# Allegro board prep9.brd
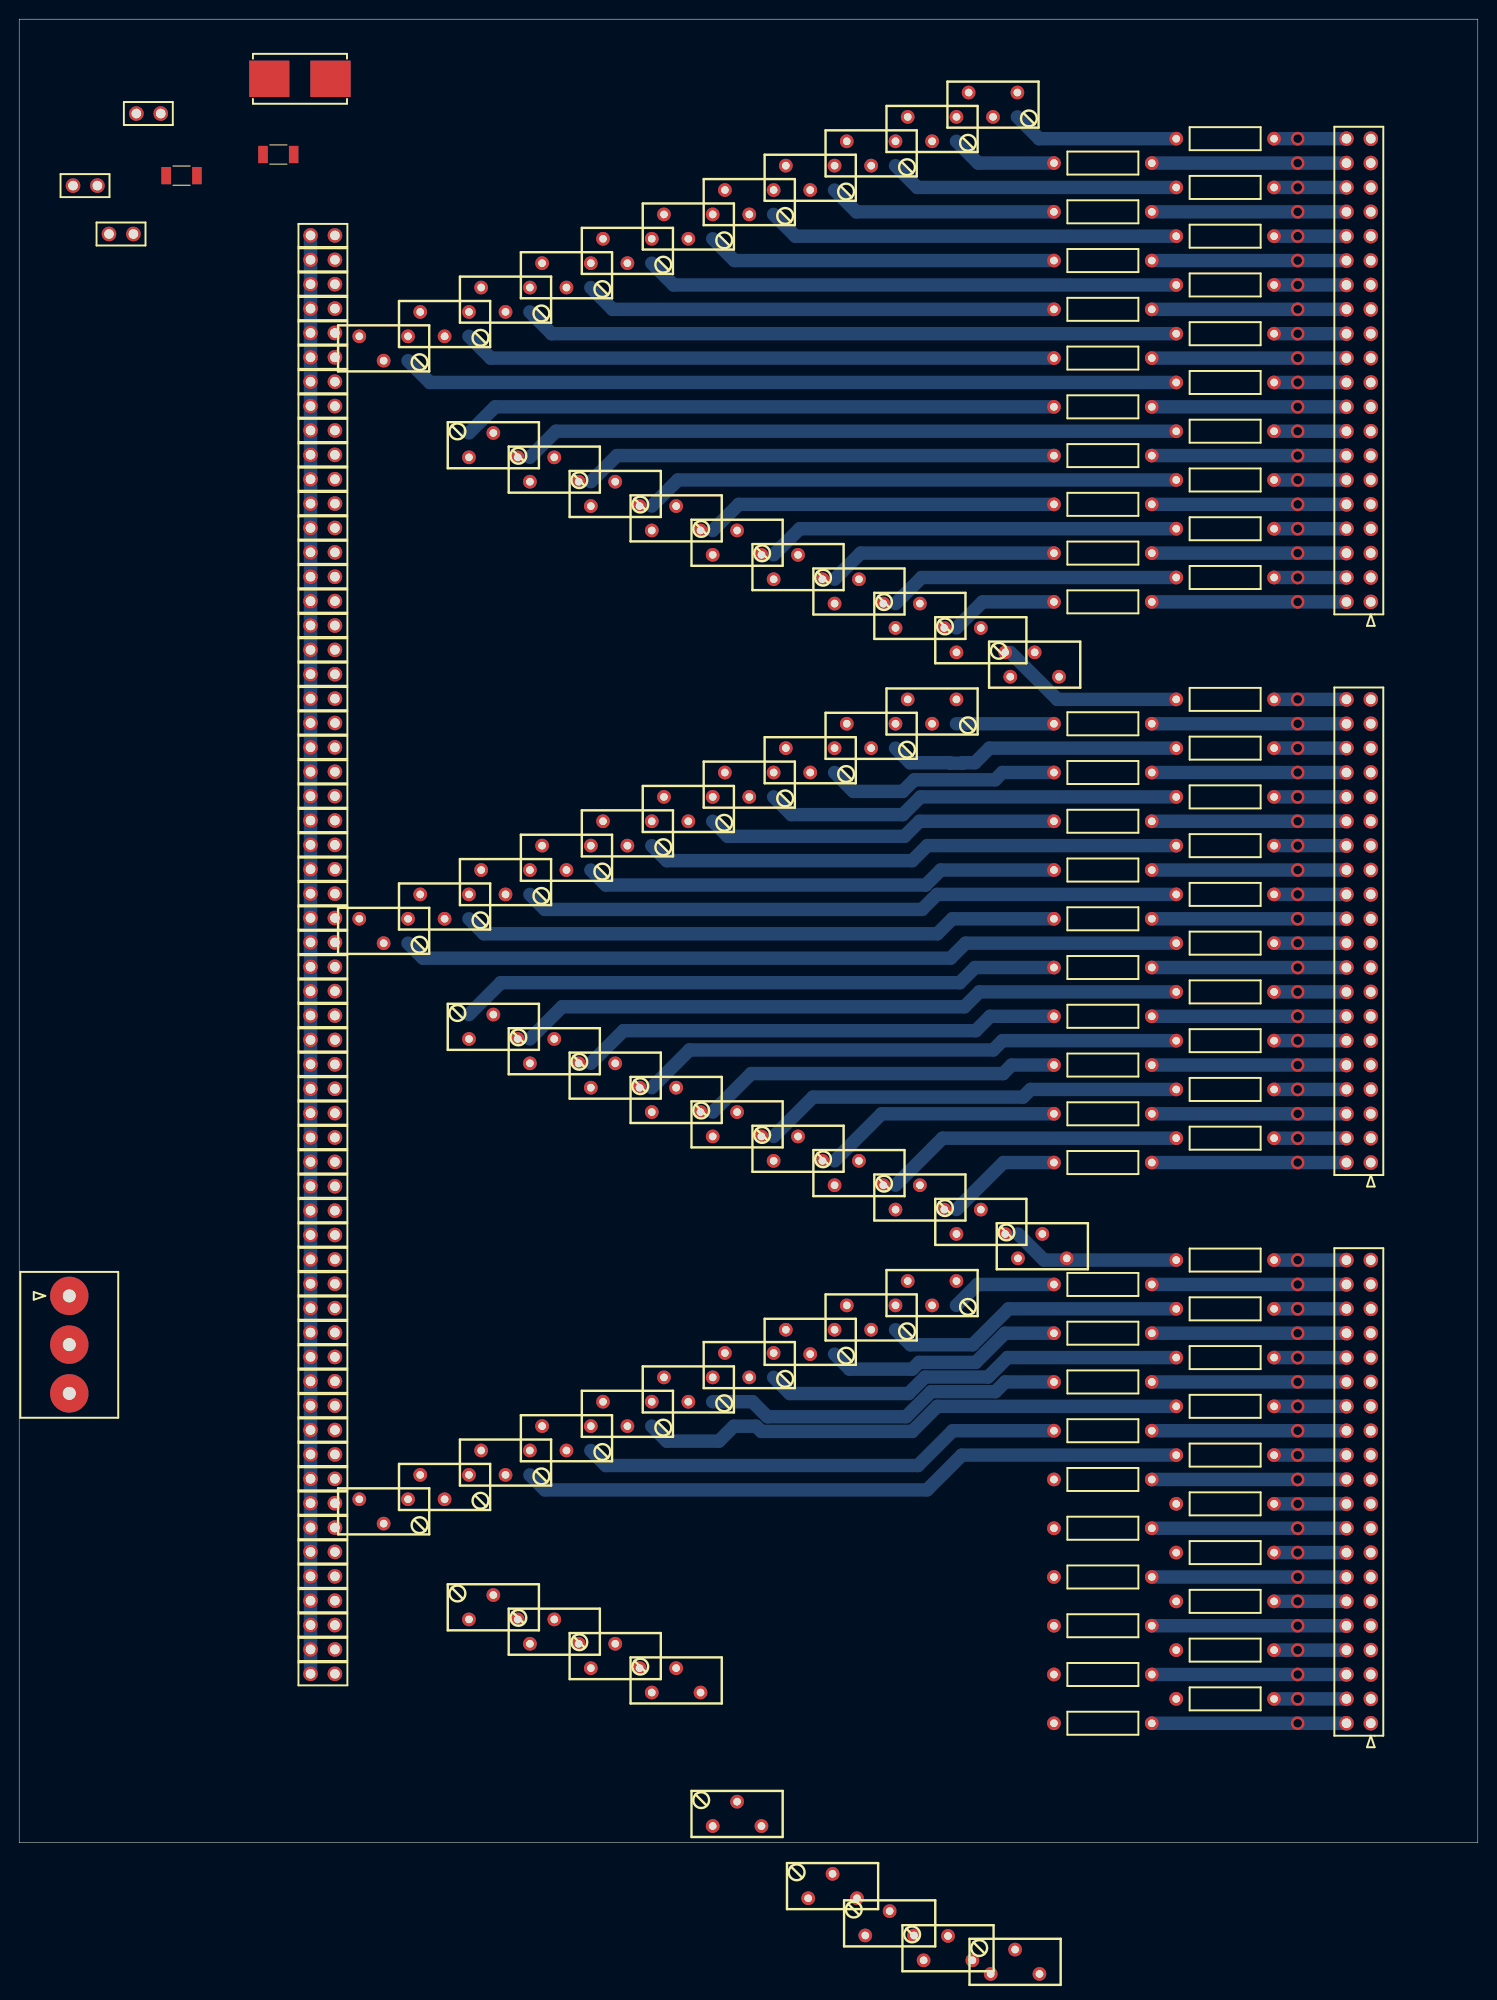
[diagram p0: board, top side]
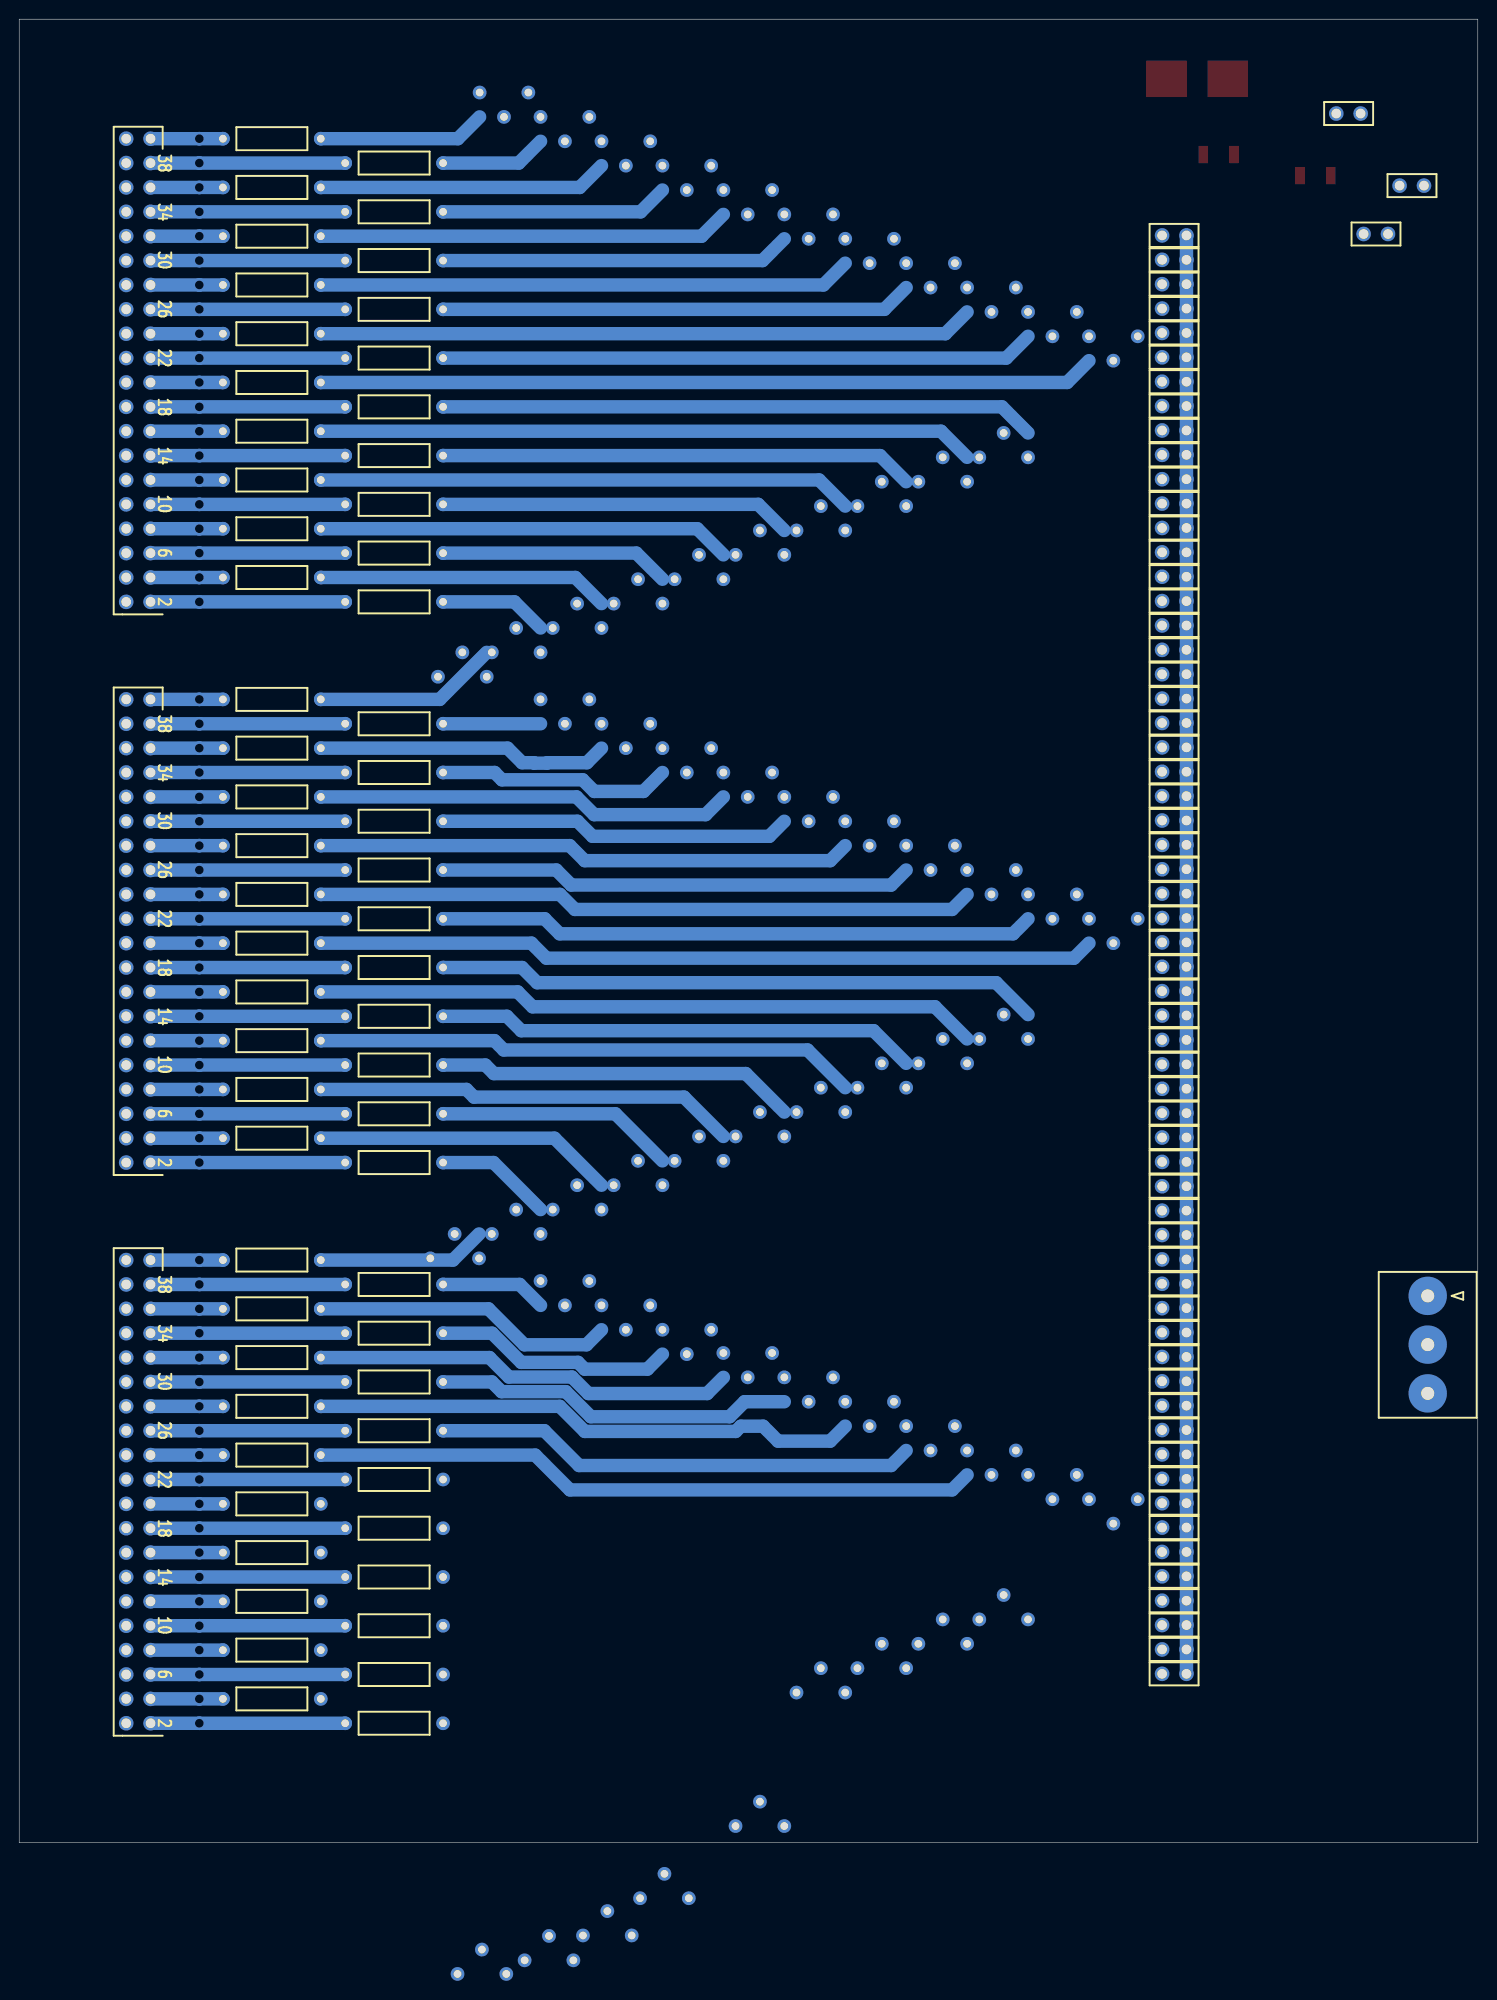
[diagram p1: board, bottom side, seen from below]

Outline 152 x 190 mm; copper layers: TOP, BOTTOM. Coordinates in mm from the lower left corner of the outline.
Outline path: 0,190 152,190 152,0 0,0 0,190

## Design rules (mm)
constraint set DEFAULT: min track width 0.15, pair gap 0.15

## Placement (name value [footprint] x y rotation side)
B1  -  [BORNIER3B5080]  5.22 56.98 270 top
C1  47u  [S32X16_1206]  15.32 173.7 0 top
C2  100n  [S32X16_1206]  25.41 175.9 0 top
F1  500mA  [FUSUPS973X503]  26.06 183.79 0 top
J1  -  [CONHE13D2X20M]  140.85 129.29 0 top
J2  -  [CONHE13D2X20M]  140.85 70.87 0 top
J3  -  [CONHE13D2X20M]  140.85 12.45 0 top
NOREF  -  []  0 0 0 top
NOREF#2  -  []  0 0 90 top
PO1  100  [POT_3296Y]  104.02 182.36 270 top
PO2  100  [POT_3296Y]  97.67 179.82 270 top
PO3  100  [POT_3296Y]  91.32 177.28 270 top
PO4  100  [POT_3296Y]  84.97 174.74 270 top
PO5  100  [POT_3296Y]  78.62 172.2 270 top
PO6  100  [POT_3296Y]  72.27 169.66 270 top
PO7  100  [POT_3296Y]  65.92 167.12 270 top
PO8  100  [POT_3296Y]  59.57 164.58 270 top
PO9  100  [POT_3296Y]  53.22 162.04 270 top
PO10  100  [POT_3296Y]  46.87 159.5 270 top
PO11  100  [POT_3296Y]  40.52 156.96 270 top
PO12  100  [POT_3296Y]  46.87 144.35 90 top
PO13  100  [POT_3296Y]  53.22 141.81 90 top
PO14  100  [POT_3296Y]  59.57 139.27 90 top
PO15  100  [POT_3296Y]  65.92 136.73 90 top
PO16  100  [POT_3296Y]  72.27 134.19 90 top
PO17  100  [POT_3296Y]  78.62 131.65 90 top
PO18  100  [POT_3296Y]  84.97 129.11 90 top
PO19  100  [POT_3296Y]  91.32 126.57 90 top
PO20  100  [POT_3296Y]  97.67 124.03 90 top
PO21  100  [POT_3296Y]  103.28 121.49 90 top
PO22  100  [POT_3296Y]  97.67 119.13 270 top
PO23  100  [POT_3296Y]  91.32 116.59 270 top
PO24  100  [POT_3296Y]  84.97 114.05 270 top
PO25  100  [POT_3296Y]  78.62 111.51 270 top
PO26  100  [POT_3296Y]  72.27 108.97 270 top
PO27  100  [POT_3296Y]  65.92 106.43 270 top
PO28  100  [POT_3296Y]  59.57 103.89 270 top
PO29  100  [POT_3296Y]  53.22 101.35 270 top
PO30  100  [POT_3296Y]  46.87 98.81 270 top
PO31  100  [POT_3296Y]  40.52 96.27 270 top
PO32  100  [POT_3296Y]  46.87 83.75 90 top
PO33  100  [POT_3296Y]  53.22 81.21 90 top
PO34  100  [POT_3296Y]  59.57 78.67 90 top
PO35  100  [POT_3296Y]  65.92 76.13 90 top
PO36  100  [POT_3296Y]  72.27 73.59 90 top
PO37  100  [POT_3296Y]  78.62 71.05 90 top
PO38  100  [POT_3296Y]  84.97 68.51 90 top
PO39  100  [POT_3296Y]  91.32 65.97 90 top
PO40  100  [POT_3296Y]  97.67 63.43 90 top
PO41  100  [POT_3296Y]  104.08 60.89 90 top
PO42  100  [POT_3296Y]  97.67 58.53 270 top
PO43  100  [POT_3296Y]  91.32 55.99 270 top
PO44  100  [POT_3296Y]  84.97 53.45 270 top
PO45  100  [POT_3296Y]  78.62 51.03 270 top
PO46  100  [POT_3296Y]  72.27 48.49 270 top
PO47  100  [POT_3296Y]  65.92 45.95 270 top
PO48  100  [POT_3296Y]  59.57 43.41 270 top
PO49  100  [POT_3296Y]  53.22 40.87 270 top
PO50  100  [POT_3296Y]  46.87 38.33 270 top
PO51  100  [POT_3296Y]  40.52 35.79 270 top
PO52  100  [POT_3296Y]  46.87 23.27 90 top
PO53  100  [POT_3296Y]  53.22 20.73 90 top
PO54  100  [POT_3296Y]  59.57 18.19 90 top
PO55  100  [POT_3296Y]  65.92 15.65 90 top
PO56  100  [POT_3296Y]  72.27 1.74 90 top
PO57  100  [POT_3296Y]  82.22 -5.78 90 top
PO58  100  [POT_3296Y]  88.17 -9.66 90 top
PO59  100  [POT_3296Y]  94.25 -12.25 90 top
PO60  100  [POT_3296Y]  101.24 -13.67 90 top
R1  100  [R100]  130.77 177.55 180 top
R2  100  [R100]  118.03 175.01 180 top
R3  100  [R100]  130.77 172.47 180 top
R4  100  [R100]  118.03 169.93 180 top
R5  100  [R100]  130.77 167.39 180 top
R6  100  [R100]  118.03 164.85 180 top
R7  100  [R100]  130.77 162.31 180 top
R8  100  [R100]  118.03 159.77 180 top
R9  100  [R100]  130.77 157.23 180 top
R10  100  [R100]  118.03 154.69 180 top
R11  100  [R100]  130.77 152.15 180 top
R12  100  [R100]  118.03 149.61 180 top
R13  100  [R100]  130.77 147.07 180 top
R14  100  [R100]  118.03 144.53 180 top
R15  100  [R100]  130.77 141.99 180 top
R16  100  [R100]  118.03 139.45 180 top
R17  100  [R100]  130.77 136.91 180 top
R18  100  [R100]  118.03 134.37 180 top
R19  100  [R100]  130.77 131.83 180 top
R20  100  [R100]  118.03 129.29 180 top
R21  100  [R100]  130.77 119.13 180 top
R22  100  [R100]  118.03 116.59 180 top
R23  100  [R100]  130.77 114.05 180 top
R24  100  [R100]  118.03 111.51 180 top
R25  100  [R100]  130.77 108.97 180 top
R26  100  [R100]  118.03 106.43 180 top
R27  100  [R100]  130.77 103.89 180 top
R28  100  [R100]  118.03 101.35 180 top
R29  100  [R100]  130.77 98.81 180 top
R30  100  [R100]  118.03 96.27 180 top
R31  100  [R100]  130.77 93.73 180 top
R32  100  [R100]  118.03 91.19 180 top
R33  100  [R100]  130.77 88.65 180 top
R34  100  [R100]  118.03 86.11 180 top
R35  100  [R100]  130.77 83.57 180 top
R36  100  [R100]  118.03 81.03 180 top
R37  100  [R100]  130.77 78.49 180 top
R38  100  [R100]  118.03 75.95 180 top
R39  100  [R100]  130.77 73.41 180 top
R40  100  [R100]  118.03 70.87 180 top
R41  100  [R100]  130.77 60.71 180 top
R42  100  [R100]  118.03 58.17 180 top
R43  100  [R100]  130.77 55.63 180 top
R44  100  [R100]  118.03 53.09 180 top
R45  100  [R100]  130.77 50.55 180 top
R46  100  [R100]  118.03 48.01 180 top
R47  100  [R100]  130.77 45.47 180 top
R48  100  [R100]  118.03 42.93 180 top
R49  100  [R100]  130.77 40.39 180 top
R50  100  [R100]  118.03 37.85 180 top
R51  100  [R100]  130.77 35.31 180 top
R52  100  [R100]  118.03 32.77 180 top
R53  100  [R100]  130.77 30.23 180 top
R54  100  [R100]  118.03 27.69 180 top
R55  100  [R100]  130.77 25.15 180 top
R56  100  [R100]  118.03 22.61 180 top
R57  100  [R100]  130.77 20.07 180 top
R58  100  [R100]  118.03 17.53 180 top
R59  100  [R100]  130.77 14.99 180 top
R60  100  [R100]  118.03 12.45 180 top
S1  -  [CONHE13D2M]  32.9 167.47 180 top
S2  -  [CONHE13D2M]  32.9 164.93 180 top
S3  -  [CONHE13D2M]  32.9 162.39 180 top
S4  -  [CONHE13D2M]  32.9 159.85 180 top
S5  -  [CONHE13D2M]  32.9 157.31 180 top
S6  -  [CONHE13D2M]  32.9 154.77 180 top
S7  -  [CONHE13D2M]  32.9 152.23 180 top
S8  -  [CONHE13D2M]  32.9 149.69 180 top
S9  -  [CONHE13D2M]  32.9 147.15 180 top
S10  -  [CONHE13D2M]  32.9 144.61 180 top
S11  -  [CONHE13D2M]  32.9 142.07 180 top
S12  -  [CONHE13D2M]  32.9 139.53 180 top
S13  -  [CONHE13D2M]  32.9 136.99 180 top
S14  -  [CONHE13D2M]  32.9 134.45 180 top
S15  -  [CONHE13D2M]  32.9 131.91 180 top
S16  -  [CONHE13D2M]  32.9 129.37 180 top
S17  -  [CONHE13D2M]  32.9 126.83 180 top
S18  -  [CONHE13D2M]  32.9 124.29 180 top
S19  -  [CONHE13D2M]  32.9 121.75 180 top
S20  -  [CONHE13D2M]  32.9 119.21 180 top
S21  -  [CONHE13D2M]  32.9 116.67 180 top
S22  -  [CONHE13D2M]  32.9 114.13 180 top
S23  -  [CONHE13D2M]  32.9 111.59 180 top
S24  -  [CONHE13D2M]  32.9 109.05 180 top
S25  -  [CONHE13D2M]  32.9 106.51 180 top
S26  -  [CONHE13D2M]  32.9 103.97 180 top
S27  -  [CONHE13D2M]  32.9 101.43 180 top
S28  -  [CONHE13D2M]  32.9 98.89 180 top
S29  -  [CONHE13D2M]  32.9 96.35 180 top
S30  -  [CONHE13D2M]  32.9 93.81 180 top
S31  -  [CONHE13D2M]  32.9 91.27 180 top
S32  -  [CONHE13D2M]  32.9 88.73 180 top
S33  -  [CONHE13D2M]  32.9 86.19 180 top
S34  -  [CONHE13D2M]  32.9 83.65 180 top
S35  -  [CONHE13D2M]  32.9 81.1 180 top
S36  -  [CONHE13D2M]  32.9 78.56 180 top
S37  -  [CONHE13D2M]  32.9 76.02 180 top
S38  -  [CONHE13D2M]  32.9 73.48 180 top
S39  -  [CONHE13D2M]  32.9 70.94 180 top
S40  -  [CONHE13D2M]  32.9 68.4 180 top
S41  -  [CONHE13D2M]  32.9 65.86 180 top
S42  -  [CONHE13D2M]  32.9 63.32 180 top
S43  -  [CONHE13D2M]  32.9 60.78 180 top
S44  -  [CONHE13D2M]  32.9 58.24 180 top
S45  -  [CONHE13D2M]  32.9 55.7 180 top
S46  -  [CONHE13D2M]  32.9 53.16 180 top
S47  -  [CONHE13D2M]  32.9 50.62 180 top
S48  -  [CONHE13D2M]  32.9 48.08 180 top
S49  -  [CONHE13D2M]  32.9 45.54 180 top
S50  -  [CONHE13D2M]  32.9 43 180 top
S51  -  [CONHE13D2M]  32.9 40.46 180 top
S52  -  [CONHE13D2M]  32.9 37.92 180 top
S53  -  [CONHE13D2M]  32.9 35.38 180 top
S54  -  [CONHE13D2M]  32.9 32.84 180 top
S55  -  [CONHE13D2M]  32.9 30.3 180 top
S56  -  [CONHE13D2M]  32.9 27.76 180 top
S57  -  [CONHE13D2M]  32.9 25.22 180 top
S58  -  [CONHE13D2M]  32.9 22.68 180 top
S59  -  [CONHE13D2M]  32.9 20.14 180 top
S60  -  [CONHE13D2M]  32.9 17.6 180 top
S61  -  [CONHE13D2M]  5.61 172.66 0 top
S62  -  [CONHE13D2M]  12.21 180.17 0 top
S63  -  [CONHE13D2M]  9.36 167.62 0 top

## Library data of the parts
B1 = BORNIER3B: part number: BORNIER3B5080
C1 = CAPA: part number: CAPA-47U,C1206S6.3V20%
C2 = CAPA: part number: CAPA-100N,C1206S50V5%
F1 = FUSUP2P: part number: FUSUP2P-500MA,CMS
J1-J3 = CON40P: part number: CON40P-HE13D
PO1-PO60 = POT: part number: POT-100,1/2W11T_D
R1-R60 = RGEN: part number: RGEN-100,M500MW5%
S1-S63 = STRAP: part number: STRAP-2X1

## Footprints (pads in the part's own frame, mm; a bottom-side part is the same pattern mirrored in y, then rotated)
BORNIER3B5080
  round 4 hole 1.35: 1(0,0) 2(5.08,0) 3(10.16,0)
CONHE13D2M
  round 1.52 hole 1: 1(0,0) 2(2.54,0)
CONHE13D2X20M
  round 1.52 hole 1: 1(0,0) 2(-2.54,0) 3(0,2.54) 4(-2.54,2.54) 5(0,5.08) 6(-2.54,5.08) 7(0,7.62) 8(-2.54,7.62) 9(0,10.16) 10(-2.54,10.16) 11(0,12.7) 12(-2.54,12.7) 13(0,15.24) 14(-2.54,15.24) 15(0,17.78) 16(-2.54,17.78) 17(0,20.32) 18(-2.54,20.32) 19(0,22.86) 20(-2.54,22.86) 21(0,25.4) 22(-2.54,25.4) 23(0,27.94) 24(-2.54,27.94) 25(0,30.48) 26(-2.54,30.48) 27(0,33.02) 28(-2.54,33.02) 29(0,35.56) 30(-2.54,35.56) 31(0,38.1) 32(-2.54,38.1) 33(0,40.64) 34(-2.54,40.64) 35(0,43.18) 36(-2.54,43.18) 37(0,45.72) 38(-2.54,45.72) 39(0,48.26) 40(-2.54,48.26)
FUSUPS973X503
  rect 4.2x3.8 smd: 1(0,0) 2(6.38,0)
POT_3296Y
  round 1.43 hole 0.8: 1(0,0) 2(2.54,-2.54) 3(0,-5.08)
R100
  round 1.43 hole 0.8: 1(0,0) 2(10.2,0)
S32X16_1206
  rect 1x1.8 smd: 1(0,0) 2(3.2,0)

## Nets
GND: B1.1 B1.2 C2.1 J1.1 J1.3 J1.5 J1.7 J1.9 J1.11 J1.13 J1.15 J1.17 J1.19 J1.21 J1.23 J1.25 J1.27 J1.29 J1.31 J1.33 J1.35 J1.37 J1.39 J2.1 J2.3 J2.5 J2.7 J2.9 J2.11 J2.13 J2.15 J2.17 J2.19 J2.21 J2.23 J2.25 J2.27 J2.29 J2.31 J2.33 J2.35 J2.37 J2.39 J3.1 J3.3 J3.5 J3.7 J3.9 J3.11 J3.13 J3.15 J3.17 J3.19 J3.21 J3.23 J3.25 J3.27 J3.29 J3.31 J3.33 J3.35 J3.37 J3.39 S62.2(B)
AC1: S61.2(B)
UNNAMED_1_BORNIER3B_I185_C: B1.3(C) F1.1
UNNAMED_1_CAPA_I190_B: C2.2(B<0>) S63.2(B)
UNNAMED_1_CON40P_I1_A: J1.10(A<9>) R16.1
UNNAMED_1_CON40P_I1_A_1: J1.8 R17.1
UNNAMED_1_CON40P_I1_A_2: J1.6 R18.1
UNNAMED_1_CON40P_I1_A_3: J1.4 R19.1
UNNAMED_1_CON40P_I1_A_4: J1.40 R1.1
UNNAMED_1_CON40P_I1_A_5: J1.38 R2.1
UNNAMED_1_CON40P_I1_A_6: J1.36 R3.1
UNNAMED_1_CON40P_I1_A_7: J1.34 R4.1
UNNAMED_1_CON40P_I1_A_8: J1.32 R5.1
UNNAMED_1_CON40P_I1_A_9: J1.30 R6.1
UNNAMED_1_CON40P_I1_A_10: J1.28 R7.1
UNNAMED_1_CON40P_I1_A_11: J1.26 R8.1
UNNAMED_1_CON40P_I1_A_12: J1.24 R9.1
UNNAMED_1_CON40P_I1_A_13: J1.22 R10.1
UNNAMED_1_CON40P_I1_A_14: J1.2 R20.1
UNNAMED_1_CON40P_I1_A_15: J1.20 R11.1
UNNAMED_1_CON40P_I1_A_16: J1.18 R12.1
UNNAMED_1_CON40P_I1_A_17: J1.16 R13.1
UNNAMED_1_CON40P_I1_A_18: J1.14 R14.1
UNNAMED_1_CON40P_I1_A_19: J1.12 R15.1
UNNAMED_1_CON40P_I2_A: J3.28 R47.1
UNNAMED_1_CON40P_I2_A_1: J3.30 R46.1
UNNAMED_1_CON40P_I2_A_2: J3.38 R42.1
UNNAMED_1_CON40P_I2_A_3: J3.32 R45.1
UNNAMED_1_CON40P_I2_A_4: J3.34 R44.1
UNNAMED_1_CON40P_I2_A_5: J3.36 R43.1
UNNAMED_1_CON40P_I2_A_6: J3.40 R41.1
UNNAMED_1_CON40P_I2_A_7: J3.6 R58.1
UNNAMED_1_CON40P_I2_A_8: J3.8 R57.1
UNNAMED_1_CON40P_I2_A_9: J3.4 R59.1
UNNAMED_1_CON40P_I2_A_10: J3.2 R60.1
UNNAMED_1_CON40P_I2_A_11: J3.10(A<9>) R56.1
UNNAMED_1_CON40P_I2_A_12: J3.12 R55.1
UNNAMED_1_CON40P_I2_A_13: J3.14 R54.1
UNNAMED_1_CON40P_I2_A_14: J3.16 R53.1
UNNAMED_1_CON40P_I2_A_15: J3.18 R52.1
UNNAMED_1_CON40P_I2_A_16: J3.20 R51.1
UNNAMED_1_CON40P_I2_A_17: J3.22 R50.1
UNNAMED_1_CON40P_I2_A_18: J3.24 R49.1
UNNAMED_1_CON40P_I2_A_19: J3.26 R48.1
UNNAMED_1_CON40P_I3_A: J2.28 R27.1
UNNAMED_1_CON40P_I3_A_1: J2.30 R26.1
UNNAMED_1_CON40P_I3_A_2: J2.38 R22.1
UNNAMED_1_CON40P_I3_A_3: J2.32 R25.1
UNNAMED_1_CON40P_I3_A_4: J2.34 R24.1
UNNAMED_1_CON40P_I3_A_5: J2.36 R23.1
UNNAMED_1_CON40P_I3_A_6: J2.40 R21.1
UNNAMED_1_CON40P_I3_A_7: J2.6 R38.1
UNNAMED_1_CON40P_I3_A_8: J2.8 R37.1
UNNAMED_1_CON40P_I3_A_9: J2.4 R39.1
UNNAMED_1_CON40P_I3_A_10: J2.2 R40.1
UNNAMED_1_CON40P_I3_A_11: J2.10(A<9>) R36.1
UNNAMED_1_CON40P_I3_A_12: J2.12 R35.1
UNNAMED_1_CON40P_I3_A_13: J2.14 R34.1
UNNAMED_1_CON40P_I3_A_14: J2.16 R33.1
UNNAMED_1_CON40P_I3_A_15: J2.18 R32.1
UNNAMED_1_CON40P_I3_A_16: J2.20 R31.1
UNNAMED_1_CON40P_I3_A_17: J2.22 R30.1
UNNAMED_1_CON40P_I3_A_18: J2.24 R29.1
UNNAMED_1_CON40P_I3_A_19: J2.26 R28.1
UNNAMED_1_FUSUP2P_I186_B: F1.2(B) S61.1 S62.1 S63.1
UNNAMED_1_POT_I5_A: PO1.1 S1.1
UNNAMED_1_POT_I5_B: PO1.2 R1.2(B<0>)
UNNAMED_1_POT_I7_A: PO2.1 S2.1
UNNAMED_1_POT_I7_B: PO2.2 R2.2(B<0>)
UNNAMED_1_POT_I26_A: PO3.1 S3.1
UNNAMED_1_POT_I26_B: PO3.2 R3.2(B<0>)
UNNAMED_1_POT_I27_A: PO4.1 S4.1
UNNAMED_1_POT_I27_B: PO4.2 R4.2(B<0>)
UNNAMED_1_POT_I28_A: PO5.1 S5.1
UNNAMED_1_POT_I28_B: PO5.2 R5.2(B<0>)
UNNAMED_1_POT_I29_A: PO6.1 S6.1
UNNAMED_1_POT_I29_B: PO6.2 R6.2(B<0>)
UNNAMED_1_POT_I30_A: PO7.1 S7.1
UNNAMED_1_POT_I30_B: PO7.2 R7.2(B<0>)
UNNAMED_1_POT_I31_A: PO8.1 S8.1
UNNAMED_1_POT_I31_B: PO8.2 R8.2(B<0>)
UNNAMED_1_POT_I32_A: PO9.1 S9.1
UNNAMED_1_POT_I32_B: PO9.2 R9.2(B<0>)
UNNAMED_1_POT_I33_A: PO10.1 S10.1
UNNAMED_1_POT_I33_B: PO10.2 R10.2(B<0>)
UNNAMED_1_POT_I34_A: PO11.1 S11.1
UNNAMED_1_POT_I34_B: PO11.2 R11.2(B<0>)
UNNAMED_1_POT_I35_A: PO12.1 S12.1
UNNAMED_1_POT_I35_B: PO12.2 R12.2(B<0>)
UNNAMED_1_POT_I36_A: PO13.1 S13.1
UNNAMED_1_POT_I36_B: PO13.2 R13.2(B<0>)
UNNAMED_1_POT_I37_A: PO14.1 S14.1
UNNAMED_1_POT_I37_B: PO14.2 R14.2(B<0>)
UNNAMED_1_POT_I38_A: PO15.1 S15.1
UNNAMED_1_POT_I38_B: PO15.2 R15.2(B<0>)
UNNAMED_1_POT_I39_A: PO16.1 S16.1
UNNAMED_1_POT_I39_B: PO16.2 R16.2(B<0>)
UNNAMED_1_POT_I40_A: PO17.1 S17.1
UNNAMED_1_POT_I40_B: PO17.2 R17.2(B<0>)
UNNAMED_1_POT_I41_A: PO18.1 S18.1
UNNAMED_1_POT_I41_B: PO18.2 R18.2(B<0>)
UNNAMED_1_POT_I42_A: PO19.1 S19.1
UNNAMED_1_POT_I42_B: PO19.2 R19.2(B<0>)
UNNAMED_1_POT_I43_A: PO20.1 S20.1
UNNAMED_1_POT_I43_B: PO20.2 R20.2(B<0>)
UNNAMED_1_POT_I44_A: PO40.1 S40.1
UNNAMED_1_POT_I44_B: PO40.2 R40.2(B<0>)
UNNAMED_1_POT_I45_A: PO39.1 S39.1
UNNAMED_1_POT_I45_B: PO39.2 R39.2(B<0>)
UNNAMED_1_POT_I46_A: PO38.1 S38.1
UNNAMED_1_POT_I46_B: PO38.2 R38.2(B<0>)
UNNAMED_1_POT_I47_A: PO33.1 S33.1
UNNAMED_1_POT_I47_B: PO33.2 R33.2(B<0>)
UNNAMED_1_POT_I48_A: PO32.1 S32.1
UNNAMED_1_POT_I48_B: PO32.2 R32.2(B<0>)
UNNAMED_1_POT_I49_A: PO31.1 S31.1
UNNAMED_1_POT_I49_B: PO31.2 R31.2(B<0>)
UNNAMED_1_POT_I50_A: PO30.1 S30.1
UNNAMED_1_POT_I50_B: PO30.2 R30.2(B<0>)
UNNAMED_1_POT_I51_A: PO29.1 S29.1
UNNAMED_1_POT_I51_B: PO29.2 R29.2(B<0>)
UNNAMED_1_POT_I52_A: PO27.1 S27.1
UNNAMED_1_POT_I52_B: PO27.2 R27.2(B<0>)
UNNAMED_1_POT_I53_A: PO28.1 S28.1
UNNAMED_1_POT_I53_B: PO28.2 R28.2(B<0>)
UNNAMED_1_POT_I54_A: PO26.1 S26.1
UNNAMED_1_POT_I54_B: PO26.2 R26.2(B<0>)
UNNAMED_1_POT_I55_A: PO25.1 S25.1
UNNAMED_1_POT_I55_B: PO25.2 R25.2(B<0>)
UNNAMED_1_POT_I56_A: PO24.1 S24.1
UNNAMED_1_POT_I56_B: PO24.2 R24.2(B<0>)
UNNAMED_1_POT_I57_A: PO22.1 S22.1
UNNAMED_1_POT_I57_B: PO22.2 R22.2(B<0>)
UNNAMED_1_POT_I58_A: PO21.1 S21.1
UNNAMED_1_POT_I58_B: PO21.2 R21.2(B<0>)
UNNAMED_1_POT_I59_A: PO23.1 S23.1
UNNAMED_1_POT_I59_B: PO23.2 R23.2(B<0>)
UNNAMED_1_POT_I72_A: PO37.1 S37.1
UNNAMED_1_POT_I72_B: PO37.2 R37.2(B<0>)
UNNAMED_1_POT_I73_A: PO36.1 S36.1
UNNAMED_1_POT_I73_B: PO36.2 R36.2(B<0>)
UNNAMED_1_POT_I74_A: PO35.1 S35.1
UNNAMED_1_POT_I74_B: PO35.2 R35.2(B<0>)
UNNAMED_1_POT_I75_A: PO34.1 S34.1
UNNAMED_1_POT_I75_B: PO34.2 R34.2(B<0>)
UNNAMED_1_POT_I84_A: PO60.1 S60.1
UNNAMED_1_POT_I84_B: PO60.2 R60.2(B<0>)
UNNAMED_1_POT_I85_A: PO59.1 S59.1
UNNAMED_1_POT_I85_B: PO59.2 R59.2(B<0>)
UNNAMED_1_POT_I86_A: PO58.1 S58.1
UNNAMED_1_POT_I86_B: PO58.2 R58.2(B<0>)
UNNAMED_1_POT_I87_A: PO53.1 S53.1
UNNAMED_1_POT_I87_B: PO53.2 R53.2(B<0>)
UNNAMED_1_POT_I88_A: PO52.1 S52.1
UNNAMED_1_POT_I88_B: PO52.2 R52.2(B<0>)
UNNAMED_1_POT_I89_A: PO51.1 S51.1
UNNAMED_1_POT_I89_B: PO51.2 R51.2(B<0>)
UNNAMED_1_POT_I90_A: PO50.1 S50.1
UNNAMED_1_POT_I90_B: PO50.2 R50.2(B<0>)
UNNAMED_1_POT_I91_A: PO49.1 S49.1
UNNAMED_1_POT_I91_B: PO49.2 R49.2(B<0>)
UNNAMED_1_POT_I92_A: PO47.1 S47.1
UNNAMED_1_POT_I92_B: PO47.2 R47.2(B<0>)
UNNAMED_1_POT_I93_A: PO48.1 S48.1
UNNAMED_1_POT_I93_B: PO48.2 R48.2(B<0>)
UNNAMED_1_POT_I94_A: PO46.1 S46.1
UNNAMED_1_POT_I94_B: PO46.2 R46.2(B<0>)
UNNAMED_1_POT_I95_A: PO45.1 S45.1
UNNAMED_1_POT_I95_B: PO45.2 R45.2(B<0>)
UNNAMED_1_POT_I96_A: PO44.1 S44.1
UNNAMED_1_POT_I96_B: PO44.2 R44.2(B<0>)
UNNAMED_1_POT_I97_A: PO42.1 S42.1
UNNAMED_1_POT_I97_B: PO42.2 R42.2(B<0>)
UNNAMED_1_POT_I98_A: PO41.1 S41.1
UNNAMED_1_POT_I98_B: PO41.2 R41.2(B<0>)
UNNAMED_1_POT_I99_A: PO43.1 S43.1
UNNAMED_1_POT_I99_B: PO43.2 R43.2(B<0>)
UNNAMED_1_POT_I112_A: PO57.1 S57.1
UNNAMED_1_POT_I112_B: PO57.2 R57.2(B<0>)
UNNAMED_1_POT_I113_A: PO56.1 S56.1
UNNAMED_1_POT_I113_B: PO56.2 R56.2(B<0>)
UNNAMED_1_POT_I114_A: PO55.1 S55.1
UNNAMED_1_POT_I114_B: PO55.2 R55.2(B<0>)
UNNAMED_1_POT_I115_A: PO54.1 S54.1
UNNAMED_1_POT_I115_B: PO54.2 R54.2(B<0>)
UNNAMED_1_STRAP_I125_B: S1.2(B) S2.2(B) S3.2(B) S4.2(B) S5.2(B) S6.2(B) S7.2(B) S8.2(B) S9.2(B) S10.2(B) S11.2(B) S12.2(B) S13.2(B) S14.2(B) S15.2(B) S16.2(B) S17.2(B) S18.2(B) S19.2(B) S20.2(B) S21.2(B) S22.2(B) S23.2(B) S24.2(B) S25.2(B) S26.2(B) S27.2(B) S28.2(B) S29.2(B) S30.2(B) S31.2(B) S32.2(B) S33.2(B) S34.2(B) S35.2(B) S36.2(B) S37.2(B) S38.2(B) S39.2(B) S40.2(B) S41.2(B) S42.2(B) S43.2(B) S44.2(B) S45.2(B) S46.2(B) S47.2(B) S48.2(B) S49.2(B) S50.2(B) S51.2(B) S52.2(B) S53.2(B) S54.2(B) S55.2(B) S56.2(B) S57.2(B) S58.2(B) S59.2(B) S60.2(B)

Pads without a net: C1 1 2; PO1 3; PO2 3; PO3 3; PO4 3; PO5 3; PO6 3; PO7 3; PO8 3; PO9 3; PO10 3; PO11 3; PO12 3; PO13 3; PO14 3; PO15 3; PO16 3; PO17 3; PO18 3; PO19 3; PO20 3; PO21 3; PO22 3; PO23 3; PO24 3; PO25 3; PO26 3; PO27 3; PO28 3; PO29 3; PO30 3; PO31 3; PO32 3; PO33 3; PO34 3; PO35 3; PO36 3; PO37 3; PO38 3; PO39 3; PO40 3; PO41 3; PO42 3; PO43 3; PO44 3; PO45 3; PO46 3; PO47 3; PO48 3; PO49 3; PO50 3; PO51 3; PO52 3; PO53 3; PO54 3; PO55 3; PO56 3; PO57 3; PO58 3; PO59 3; PO60 3

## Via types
v1: diameter 1.42, hole 0.9, TOP to BOTTOM, 60 vias

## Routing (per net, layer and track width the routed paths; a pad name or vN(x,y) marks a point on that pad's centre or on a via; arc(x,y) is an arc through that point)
UNNAMED_1_CON40P_I1_A: length 20.3
  BOTTOM w1.4: R16.1 v1(133.23,139.45) J1.10
UNNAMED_1_CON40P_I1_A_1: length 7.5
  BOTTOM w1.4: R17.1 v1(133.23,136.91) J1.8
UNNAMED_1_CON40P_I1_A_2: length 20.3
  BOTTOM w1.4: R18.1 v1(133.23,134.37) J1.6
UNNAMED_1_CON40P_I1_A_3: length 7.5
  BOTTOM w1.4: R19.1 v1(133.23,131.83) J1.4
UNNAMED_1_CON40P_I1_A_4: length 7.5
  BOTTOM w1.4: J1.40 v1(133.23,177.55) R1.1
UNNAMED_1_CON40P_I1_A_5: length 20.3
  BOTTOM w1.4: R2.1 v1(133.23,175.01) J1.38
UNNAMED_1_CON40P_I1_A_6: length 7.5
  BOTTOM w1.4: J1.36 v1(133.23,172.47) R3.1
UNNAMED_1_CON40P_I1_A_7: length 20.3
  BOTTOM w1.4: R4.1 v1(133.23,169.93) J1.34
UNNAMED_1_CON40P_I1_A_8: length 7.5
  BOTTOM w1.4: R5.1 v1(133.23,167.39) J1.32
UNNAMED_1_CON40P_I1_A_9: length 20.3
  BOTTOM w1.4: J1.30 v1(133.23,164.85) R6.1
UNNAMED_1_CON40P_I1_A_10: length 7.5
  BOTTOM w1.4: R7.1 v1(133.23,162.31) J1.28
UNNAMED_1_CON40P_I1_A_11: length 20.3
  BOTTOM w1.4: J1.26 v1(133.23,159.77) R8.1
UNNAMED_1_CON40P_I1_A_12: length 7.5
  BOTTOM w1.4: R9.1 v1(133.23,157.23) J1.24
UNNAMED_1_CON40P_I1_A_13: length 20.3
  BOTTOM w1.4: R10.1 v1(133.23,154.69) J1.22
UNNAMED_1_CON40P_I1_A_14: length 20.3
  BOTTOM w1.4: J1.2 v1(133.23,129.29) R20.1
UNNAMED_1_CON40P_I1_A_15: length 7.5
  BOTTOM w1.4: R11.1 v1(133.23,152.15) J1.20
UNNAMED_1_CON40P_I1_A_16: length 20.3
  BOTTOM w1.4: J1.18 v1(133.23,149.61) R12.1
UNNAMED_1_CON40P_I1_A_17: length 7.5
  BOTTOM w1.4: R13.1 v1(133.23,147.07) J1.16
UNNAMED_1_CON40P_I1_A_18: length 20.3
  BOTTOM w1.4: J1.14 v1(133.23,144.53) R14.1
UNNAMED_1_CON40P_I1_A_19: length 7.5
  BOTTOM w1.4: J1.12 v1(133.23,141.99) R15.1
UNNAMED_1_CON40P_I2_A: length 7.5
  BOTTOM w1.4: J3.28 v1(133.23,45.47) R47.1
UNNAMED_1_CON40P_I2_A_1: length 20.3
  BOTTOM w1.4: J3.30 v1(133.23,48.01) R46.1
UNNAMED_1_CON40P_I2_A_2: length 20.3
  BOTTOM w1.4: R42.1 v1(133.23,58.17) J3.38
UNNAMED_1_CON40P_I2_A_3: length 7.5
  BOTTOM w1.4: R45.1 v1(133.23,50.55) J3.32
UNNAMED_1_CON40P_I2_A_4: length 20.3
  BOTTOM w1.4: R44.1 v1(133.23,53.09) J3.34
UNNAMED_1_CON40P_I2_A_5: length 7.5
  BOTTOM w1.4: J3.36 v1(133.23,55.63) R43.1
UNNAMED_1_CON40P_I2_A_6: length 7.5
  BOTTOM w1.4: R41.1 v1(133.23,60.71) J3.40
UNNAMED_1_CON40P_I2_A_7: length 20.3
  BOTTOM w1.4: R58.1 v1(133.23,17.53) J3.6
UNNAMED_1_CON40P_I2_A_8: length 7.5
  BOTTOM w1.4: R57.1 v1(133.23,20.07) J3.8
UNNAMED_1_CON40P_I2_A_9: length 7.5
  BOTTOM w1.4: R59.1 v1(133.23,14.99) J3.4
UNNAMED_1_CON40P_I2_A_10: length 20.3
  BOTTOM w1.4: J3.2 v1(133.23,12.45) R60.1
UNNAMED_1_CON40P_I2_A_11: length 20.3
  BOTTOM w1.4: J3.10 v1(133.23,22.61) R56.1
UNNAMED_1_CON40P_I2_A_12: length 7.5
  BOTTOM w1.4: R55.1 v1(133.23,25.15) J3.12
UNNAMED_1_CON40P_I2_A_13: length 20.3
  BOTTOM w1.4: J3.14 v1(133.23,27.69) R54.1
UNNAMED_1_CON40P_I2_A_14: length 7.5
  BOTTOM w1.4: J3.16 v1(133.23,30.23) R53.1
UNNAMED_1_CON40P_I2_A_15: length 20.3
  BOTTOM w1.4: R52.1 v1(133.23,32.77) J3.18
UNNAMED_1_CON40P_I2_A_16: length 7.5
  BOTTOM w1.4: J3.20 v1(133.23,35.31) R51.1
UNNAMED_1_CON40P_I2_A_17: length 20.3
  BOTTOM w1.4: R50.1 v1(133.23,37.85) J3.22
UNNAMED_1_CON40P_I2_A_18: length 7.5
  BOTTOM w1.4: R49.1 v1(133.23,40.39) J3.24
UNNAMED_1_CON40P_I2_A_19: length 20.3
  BOTTOM w1.4: R48.1 v1(133.23,42.93) J3.26
UNNAMED_1_CON40P_I3_A: length 7.5
  BOTTOM w1.4: R27.1 v1(133.23,103.89) J2.28
UNNAMED_1_CON40P_I3_A_1: length 20.3
  BOTTOM w1.4: J2.30 v1(133.23,106.43) R26.1
UNNAMED_1_CON40P_I3_A_2: length 20.3
  BOTTOM w1.4: R22.1 v1(133.23,116.59) J2.38
UNNAMED_1_CON40P_I3_A_3: length 7.5
  BOTTOM w1.4: R25.1 v1(133.23,108.97) J2.32
UNNAMED_1_CON40P_I3_A_4: length 20.3
  BOTTOM w1.4: J2.34 v1(133.23,111.51) R24.1
UNNAMED_1_CON40P_I3_A_5: length 7.5
  BOTTOM w1.4: R23.1 v1(133.23,114.05) J2.36
UNNAMED_1_CON40P_I3_A_6: length 7.5
  BOTTOM w1.4: J2.40 v1(133.23,119.13) R21.1
UNNAMED_1_CON40P_I3_A_7: length 20.3
  BOTTOM w1.4: J2.6 v1(133.23,75.95) R38.1
UNNAMED_1_CON40P_I3_A_8: length 7.5
  BOTTOM w1.4: J2.8 v1(133.23,78.49) R37.1
UNNAMED_1_CON40P_I3_A_9: length 7.5
  BOTTOM w1.4: J2.4 v1(133.23,73.41) R39.1
UNNAMED_1_CON40P_I3_A_10: length 20.3
  BOTTOM w1.4: R40.1 v1(133.23,70.87) J2.2
UNNAMED_1_CON40P_I3_A_11: length 20.3
  BOTTOM w1.4: R36.1 v1(133.23,81.03) J2.10
UNNAMED_1_CON40P_I3_A_12: length 7.5
  BOTTOM w1.4: J2.12 v1(133.23,83.57) R35.1
UNNAMED_1_CON40P_I3_A_13: length 20.3
  BOTTOM w1.4: J2.14 v1(133.23,86.11) R34.1
UNNAMED_1_CON40P_I3_A_14: length 7.5
  BOTTOM w1.4: J2.16 v1(133.23,88.65) R33.1
UNNAMED_1_CON40P_I3_A_15: length 20.3
  BOTTOM w1.4: R32.1 v1(133.23,91.19) J2.18
UNNAMED_1_CON40P_I3_A_16: length 7.5
  BOTTOM w1.4: J2.20 v1(133.23,93.73) R31.1
UNNAMED_1_CON40P_I3_A_17: length 20.3
  BOTTOM w1.4: R30.1 v1(133.23,96.27) J2.22
UNNAMED_1_CON40P_I3_A_18: length 7.5
  BOTTOM w1.4: R29.1 v1(133.23,98.81) J2.24
UNNAMED_1_CON40P_I3_A_19: length 20.3
  BOTTOM w1.4: J2.26 v1(133.23,101.35) R28.1
UNNAMED_1_POT_I5_B: length 17.5
  BOTTOM w1.4: 104.02,179.82 106.29,177.55 R1.2
UNNAMED_1_POT_I7_B: length 11.1
  BOTTOM w1.4: 97.67,177.28 99.94,175.01 R2.2
UNNAMED_1_POT_I26_B: length 30.2
  BOTTOM w1.4: 91.32,174.74 93.59,172.47 R3.2
UNNAMED_1_POT_I27_B: length 23.8
  BOTTOM w1.4: 84.97,172.2 87.24,169.93 R4.2
UNNAMED_1_POT_I28_B: length 42.9
  BOTTOM w1.4: R5.2 80.89,167.39 78.62,169.66
UNNAMED_1_POT_I29_B: length 36.5
  BOTTOM w1.4: 72.27,167.12 74.54,164.85 R6.2
UNNAMED_1_POT_I30_B: length 55.6
  BOTTOM w1.4: 65.92,164.58 68.19,162.31 R7.2
UNNAMED_1_POT_I31_B: length 49.2
  BOTTOM w1.4: R8.2 61.84,159.77 59.57,162.04
UNNAMED_1_POT_I32_B: length 68.3
  BOTTOM w1.4: R9.2 55.49,157.23 53.22,159.5
UNNAMED_1_POT_I33_B: length 61.9
  BOTTOM w1.4: R10.2 49.14,154.69 46.87,156.96
UNNAMED_1_POT_I34_B: length 81
  BOTTOM w1.4: R11.2 42.79,152.15 40.52,154.42
UNNAMED_1_POT_I35_B: length 62.1
  BOTTOM w1.4: R12.2 49.59,149.61 46.87,146.89
UNNAMED_1_POT_I36_B: length 68.5
  BOTTOM w1.4: 53.22,144.35 55.94,147.07 R13.2
UNNAMED_1_POT_I37_B: length 49.4
  BOTTOM w1.4: 59.57,141.81 62.29,144.53 R14.2
UNNAMED_1_POT_I38_B: length 55.8
  BOTTOM w1.4: 65.92,139.27 68.64,141.99 R15.2
UNNAMED_1_POT_I39_B: length 36.7
  BOTTOM w1.4: 72.27,136.73 74.99,139.45 R16.2
UNNAMED_1_POT_I40_B: length 43.1
  BOTTOM w1.4: R17.2 81.34,136.91 78.62,134.19
UNNAMED_1_POT_I41_B: length 24
  BOTTOM w1.4: 84.97,131.65 87.69,134.37 R18.2
UNNAMED_1_POT_I42_B: length 30.4
  BOTTOM w1.4: R19.2 94.04,131.83 91.32,129.11
UNNAMED_1_POT_I43_B: length 11.3
  BOTTOM w1.4: R20.2 100.39,129.29 97.67,126.57
UNNAMED_1_POT_I44_B: length 12.2
  BOTTOM w1.4: 97.67,65.97 102.57,70.87 R40.2
UNNAMED_1_POT_I45_B: length 31.3
  BOTTOM w1.4: 91.32,68.51 96.22,73.41 R39.2
UNNAMED_1_POT_I46_B: length 24.9
  BOTTOM w1.4: R38.2 89.87,75.95 84.97,71.05
UNNAMED_1_POT_I47_B: length 69.4
  BOTTOM w1.4: R33.2 100.05,88.65 98.5,87.1 56.57,87.1 53.22,83.75
UNNAMED_1_POT_I48_B: length 63
  BOTTOM w1.4: R32.2 99.6,91.19 98.02,89.61 50.19,89.61 46.87,86.29
UNNAMED_1_POT_I49_B: length 81.3
  BOTTOM w1.4: R31.2 98.62,93.73 97.06,92.17 42.09,92.17 40.52,93.73
UNNAMED_1_POT_I50_B: length 62.3
  BOTTOM w1.4: 46.87,96.27 48.44,94.7 95.67,94.7 97.24,96.27 R30.2
UNNAMED_1_POT_I51_B: length 68.6
  BOTTOM w1.4: 53.22,98.81 54.78,97.25 94.08,97.25 95.65,98.81 R29.2
UNNAMED_1_POT_I52_B: length 55.9
  BOTTOM w1.4: 65.92,103.89 67.48,102.33 93.06,102.33 94.63,103.89 R27.2
UNNAMED_1_POT_I53_B: length 49.6
  BOTTOM w1.4: R28.2 96.03,101.35 94.47,99.78 61.13,99.78 59.57,101.35
UNNAMED_1_POT_I54_B: length 36.9
  BOTTOM w1.4: R26.2 93.82,106.43 92.25,104.86 73.83,104.86 72.27,106.43
UNNAMED_1_POT_I55_B: length 43.5
  BOTTOM w1.4: R25.2 93.93,108.97 92.08,107.12 80.47,107.12 78.62,108.97
UNNAMED_1_POT_I56_B: length 24.5
  BOTTOM w1.4: 84.97,111.51 86.94,109.54 92.07,109.54 93.28,110.75 101.69,110.75 102.45,111.51 R24.2
UNNAMED_1_POT_I57_B: length 10.2
  BOTTOM w1.4: R22.2 97.67,116.59
UNNAMED_1_POT_I58_B: length 19.3
  BOTTOM w1.4: 103.28,124.03 108.18,119.13 R21.2
UNNAMED_1_POT_I59_B: length 30.5
  BOTTOM w1.4: 91.32,114.05 92.84,112.53 96.98,112.53 97.02,112.48 98.32,112.48 98.36,112.53 99.59,112.53 101.11,114.05 R23.2
UNNAMED_1_POT_I72_B: length 44
  BOTTOM w1.4: 78.62,73.59 82.72,77.69 104.6,77.69 105.4,78.49 R37.2
UNNAMED_1_POT_I73_B: length 37.6
  BOTTOM w1.4: R36.2 103.42,81.03 102.53,80.14 76.28,80.14 72.27,76.13
UNNAMED_1_POT_I74_B: length 56.7
  BOTTOM w1.4: 65.92,78.67 69.85,82.6 101.5,82.6 102.47,83.57 R35.2
UNNAMED_1_POT_I75_B: length 50.3
  BOTTOM w1.4: 59.57,81.21 62.97,84.61 99.68,84.61 101.18,86.11 R34.2
UNNAMED_1_POT_I91_B: length 69.5
  BOTTOM w1.4: 53.22,38.33 54.78,36.77 94.61,36.77 98.23,40.39 R49.2
UNNAMED_1_POT_I92_B: length 57.2
  BOTTOM w1.4: R47.2 95.67,45.47 93.06,42.86 77.34,42.86 76.8,43.4 74.47,43.4 72.92,41.84 67.48,41.84 65.92,43.41
UNNAMED_1_POT_I93_B: length 50.4
  BOTTOM w1.4: 59.57,40.87 61.13,39.3 93.66,39.3 97.28,42.93 R48.2
UNNAMED_1_POT_I94_B: length 37.7
  BOTTOM w1.4: R46.2 102.74,48.01 101.73,47 95.04,47 92.43,44.38 77.97,44.38 76.41,45.95 72.27,45.95
UNNAMED_1_POT_I95_B: length 44.2
  BOTTOM w1.4: R45.2 102.99,50.55 100.96,48.52 94.4,48.52 92.69,46.8 80.31,46.8 78.62,48.49
UNNAMED_1_POT_I96_B: length 25.1
  BOTTOM w1.4: R44.2 102.72,53.09 99.68,50.05 93.77,50.05 93.07,49.34 86.53,49.34 84.97,50.91
UNNAMED_1_POT_I97_B: length 11.1
  BOTTOM w1.4: R42.2 99.85,58.17 97.67,55.99
UNNAMED_1_POT_I98_B: length 17.6
  BOTTOM w1.4: R41.2 106.8,60.71 104.08,63.43
UNNAMED_1_POT_I99_B: length 31.4
  BOTTOM w1.4: R43.2 103.1,55.63 99.36,51.88 92.89,51.88 91.32,53.45
UNNAMED_1_STRAP_I125_B: length 149.9
  BOTTOM w1.4: S60.2 S59.2 S58.2 S57.2 S56.2 S55.2 S54.2 S53.2 S52.2 S51.2 S50.2 S49.2 S48.2 S47.2 S46.2 S45.2 S44.2 S43.2 S42.2 S41.2 S40.2 S39.2 S38.2 S37.2 S36.2 S35.2 S34.2 S33.2 S32.2 S31.2 S30.2 S29.2 S28.2 S27.2 S26.2 S25.2 S24.2 S23.2 S22.2 S21.2 S20.2 S19.2 S18.2 S17.2 S16.2 S15.2 S14.2 S13.2 S12.2 S11.2 S10.2 S9.2 S8.2 S7.2 S6.2 S5.2 S4.2 S3.2 S2.2 S1.2
